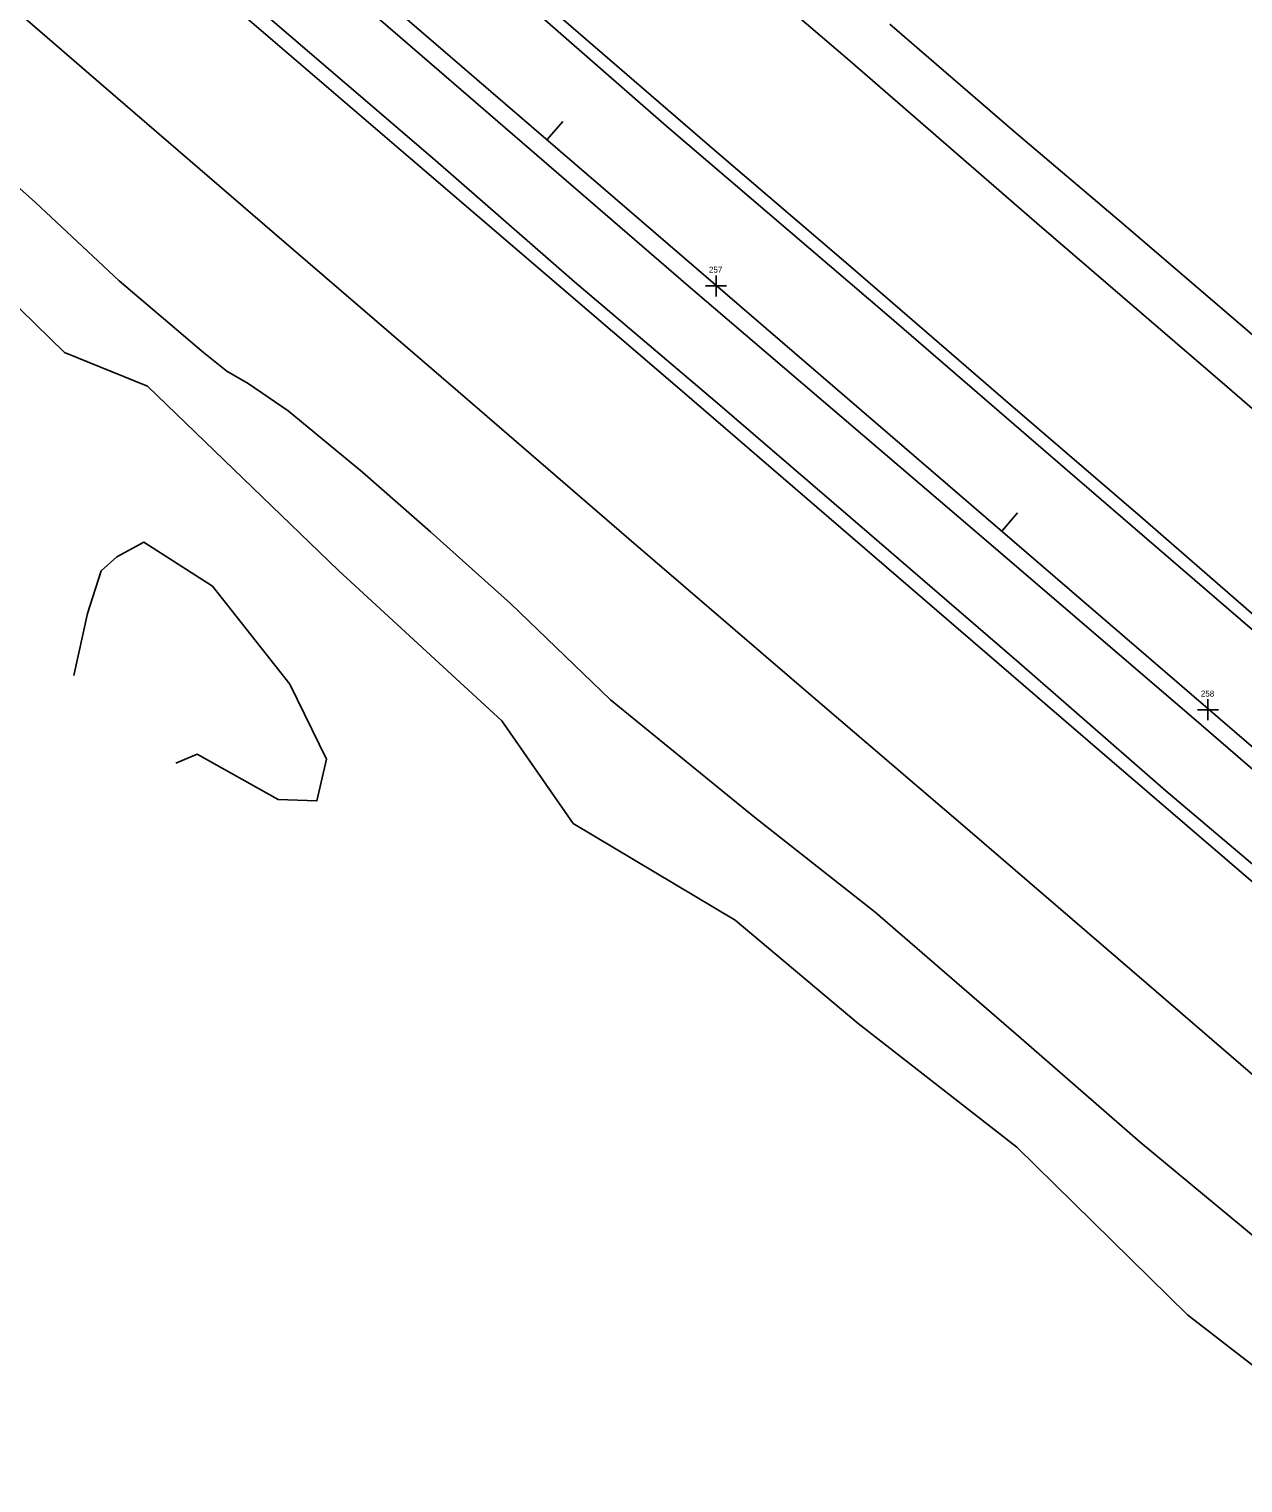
# Model space of a CAD drawing. Extents: x 2076109 to 2080761, y 592812 to 596750.
# Drawn here: x 2079809.3 to 2080011.7, y 593333.4 to 593575.6 of the extents above; entities that cross this region are included whole.
import ezdxf

# ---------------------------------------------------------------- set-up
doc = ezdxf.new("R2010")
doc.units = 0
for name, color, linetype in [('Default', 7, 'Continuous'), ('RD_EX_GuardRail', 7, 'Continuous'), ('RD_EX_Misc', 7, 'Continuous'), ('RD_EX_Road', 7, 'Continuous'), ('RD_EX_VEG', 7, 'Continuous'), ('RD_HC_Cl', 7, 'Continuous'), ('RD_HC_Data_Tic', 7, 'Continuous')]:
    doc.layers.add(name, color=color, linetype=linetype)

msp = doc.modelspace()

# ---------------------------------------------------------------- linework, layer by layer
at = {"layer": 'Default'}
for p, q in [((2079925.58, 593532.81), (2079922.08, 593532.81)), ((2079925.58, 593532.81), (2079922.08, 593532.81)), ((2079923.83, 593534.56), (2079923.83, 593531.06)), ((2079923.83, 593534.56), (2079923.83, 593531.06)), ((2080005.82, 593463.93), (2080005.82, 593460.43)), ((2080005.82, 593463.93), (2080005.82, 593460.43)), ((2080007.57, 593462.18), (2080004.07, 593462.18)), ((2080007.57, 593462.18), (2080004.07, 593462.18))]:
    msp.add_line(p, q, dxfattribs=at)
at = {"layer": 'RD_EX_GuardRail'}
msp.add_lwpolyline([(2080184.35, 593305.04), (2080148.2, 593335.86), (2080111.67, 593367.26), (2080075.44, 593398.3), (2080039.84, 593429.28), (2080003.46, 593460.74), (2079967.36, 593491.67), (2079919.17, 593532.83), (2079871.19, 593574.23), (2079835.53, 593605.02), (2079799.41, 593635.93), (2079763.16, 593666.95), (2079727.5, 593697.27), (2079690.37, 593729.2), (2079655.55, 593758.99), (2079608.01, 593799.67)], dxfattribs=at)
at = {"layer": 'RD_EX_Misc'}
for points in [[(2080217.04, 593337.18), (2080172.52, 593375.33), (2080138.87, 593404.33), (2080108.48, 593430.29), (2080078.14, 593456.52), (2080038.92, 593490.11), (2080009.05, 593515.98), (2079977.29, 593543.26), (2079946.15, 593570.28), (2079919.11, 593593.43), (2079890.41, 593617.97), (2079858.75, 593645.26), (2079821.86, 593677.15), (2079782.12, 593711.42), (2079735.64, 593751.71), (2079701.45, 593781.37), (2079664.35, 593813.72), (2079643.76, 593831.64)], [(2079627.11, 593812.28), (2079655.96, 593786.97), (2079692.98, 593754.86), (2079726.56, 593725.77), (2079758.83, 593697.63), (2079788.04, 593672.28), (2079811.24, 593652.3), (2079842, 593625.98), (2079868.07, 593603.53), (2079898.03, 593577.49), (2079923.97, 593555.11), (2079945.84, 593536.38), (2079972.92, 593513.01), (2079994.98, 593494.07), (2080016.85, 593475.02), (2080049.11, 593447.31), (2080079.81, 593420.95), (2080112.25, 593393.22), (2080144.25, 593365.64), (2080177.02, 593337.45), (2080203.16, 593314.91)], [(2080178.72, 593290.98), (2080145.52, 593319.67), (2080116.25, 593344.84), (2080082.12, 593374.03), (2080051.53, 593400.34), (2080021.2, 593426.66), (2079989.82, 593453.61), (2079954.27, 593484.21), (2079917.77, 593515.59), (2079872.88, 593554.03), (2079843.75, 593579.04), (2079811.01, 593607.11), (2079771.89, 593640.76), (2079736.28, 593671.46), (2079708.41, 593695.19), (2079678.65, 593720.6), (2079637.6, 593755.82), (2079606.82, 593782.2)], [(2079590.1, 593765.16), (2079617.13, 593742.26), (2079645.39, 593718.11), (2079673.76, 593693.67), (2079705.98, 593665.94), (2079741.28, 593635.42), (2079768.01, 593612.45), (2079794.32, 593589.74), (2079821.72, 593566.1), (2079850.25, 593541.52), (2079880.79, 593515.25), (2079909.32, 593490.67), (2079940.4, 593463.94), (2079966.11, 593441.94), (2079995.57, 593416.65), (2080039.13, 593379.08), (2080076.01, 593347.24), (2080106.97, 593320.7), (2080137.83, 593294.2), (2080162.8, 593272.51)]]:
    msp.add_lwpolyline(points, dxfattribs=at)
at = {"layer": 'RD_EX_Road'}
for points in [[(2080013.69, 593374.25), (2079994.53, 593390.12), (2079974.67, 593407.43), (2079950.37, 593428.44), (2079930.22, 593444.29), (2079906.23, 593463.83), (2079889.56, 593479.91), (2079876.23, 593491.81), (2079864.88, 593501.76), (2079852.54, 593511.97), (2079845.85, 593516.55), (2079842.28, 593518.58), (2079838.4, 593521.7), (2079824.37, 593533.64), (2079810.39, 593546.7), (2079757.88, 593593.63)], [(2079847.19, 593579.3), (2079876.99, 593553.77), (2079900.24, 593533.48), (2079923.68, 593513.62), (2079949.41, 593491.47), (2079974.36, 593470.03), (2079998.83, 593448.69), (2080024.15, 593427.25), (2080046.72, 593407.88), (2080073.17, 593385.13), (2080096.5, 593365.09), (2080125.99, 593339.59), (2080151.99, 593317.38), (2080169.44, 593302.21), (2080179.69, 593293.27)], [(2080204.43, 593311.21), (2080180.43, 593331.76), (2080159.45, 593349.86), (2080139.19, 593367.19), (2080113.07, 593389.68), (2080087.59, 593411.58), (2080058.73, 593436.21), (2080034.27, 593457.36), (2080013.24, 593475.51), (2079982.05, 593502.38), (2079952.67, 593527.69), (2079915.58, 593559.4), (2079891.77, 593580.17)], [(2079952.79, 593576.41), (2079973.53, 593558.52), (2079991.07, 593543.66), (2080010.86, 593526.69), (2080036.29, 593504.75), (2080061.97, 593482.54), (2080087.26, 593460.81), (2080111.58, 593439.6), (2080132.18, 593421.92), (2080159.11, 593398.54), (2080188.43, 593373.33), (2080218.73, 593347.44)]]:
    msp.add_lwpolyline(points, dxfattribs=at)
at = {"layer": 'RD_EX_VEG'}
for points in [[(2079741.28, 593586.6), (2079759.63, 593573.33), (2079766.05, 593568.33), (2079784.04, 593551.85), (2079798.13, 593538.37), (2079815.23, 593521.73), (2079829.05, 593516.08), (2079860.88, 593485.4), (2079888.13, 593460.36), (2079900, 593443.24), (2079927, 593427.12), (2079947.52, 593409.93), (2079973.96, 593389.29), (2080002.41, 593361.36), (2080032.72, 593337.93), (2080046.73, 593326.92), (2080056.76, 593311.95), (2080076.73, 593300.98), (2080088.77, 593291.13), (2080093.96, 593283.85), (2080096.32, 593263.66), (2080109.67, 593242.67), (2080124.71, 593229.03)], [(2079833.81, 593453.27), (2079837.37, 593454.79), (2079850.84, 593447.22), (2079857.31, 593447), (2079858.89, 593453.96), (2079852.82, 593466.44), (2079839.91, 593482.79), (2079828.45, 593490.1), (2079823.96, 593487.69), (2079821.35, 593485.32), (2079819.08, 593478.2), (2079816.81, 593467.91)], [(2079833.81, 593453.27), (2079837.37, 593454.79), (2079850.84, 593447.22), (2079857.31, 593447), (2079858.89, 593453.96), (2079852.82, 593466.44), (2079839.91, 593482.79), (2079828.45, 593490.1), (2079823.96, 593487.69), (2079821.35, 593485.32), (2079819.08, 593478.2), (2079816.81, 593467.91)]]:
    msp.add_lwpolyline(points, dxfattribs=at)
at = {"layer": 'RD_HC_Cl'}
msp.add_line((2079511.94, 593887.33), (2080761.16, 592812.48), dxfattribs=at)
at = {"layer": 'RD_HC_Data_Tic'}
for p, q in [((2079895.66, 593557.18), (2079898.27, 593560.21)), ((2079895.66, 593557.18), (2079898.27, 593560.21)), ((2079971.46, 593491.95), (2079974.07, 593494.99)), ((2079971.46, 593491.95), (2079974.07, 593494.99))]:
    msp.add_line(p, q, dxfattribs=at)

# ---------------------------------------------------------------- texts
at = {"layer": 'Default'}
for s, p in [('257', (2079922.65, 593535.01)), ('257', (2079922.65, 593535.01)), ('258', (2080004.64, 593464.38)), ('258', (2080004.64, 593464.38))]:
    msp.add_text(s, height=1, dxfattribs=at).set_placement(p)

doc.saveas('drawing.dxf')
